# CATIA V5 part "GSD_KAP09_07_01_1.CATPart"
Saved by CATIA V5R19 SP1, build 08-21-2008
Part number: GSD_REPETITION_06
Description: Beispielmodell: Duplizieren eines geometrischen Sets  Maik Hertha IT Consultants
Bounding box of the stored display mesh (mm): x -29.841 to 75.347, y -10 to 40, z 36.232 to 56.986
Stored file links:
  C:\Users\Maik\CAD Daten\modelle\gsd_buch_uebung\GSD_KAP09_07_01_END.CATPart
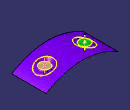
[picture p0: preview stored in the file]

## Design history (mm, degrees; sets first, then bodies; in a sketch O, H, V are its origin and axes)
AxisSystem1 "Absolute Axis System": origin (0, 0, 0), X (1, 0, 0), Y (0, 1, 0), Z (0, 0, 1)
Set1 "Work"
  Plane1: type Equation, A 0, B 1, C 0, Length -10
  Point1: type OnPlane, Support Plane1, Direction (-1, 0, 0), H -16.666, V 8.006
  Sketch1 on Plane1, origin (16.666, -10, 8.006), H (-1, 0, 0), V (0, 0, 1)
    spline S1 through (-58.6807, 28.2259) (-5.4892, 43.7462) (46.5071, 28.2259)
    curve C1
  Extrude1: Lim1 50, Lim2 0, Element1 Sketch1.C1, Direction Plane1
  Set2 "Basis"
    Point2 "Referenzpunkt.1": stored without definition
    Line1 "Ausrichtung.1": type PtDir, Direction (0, 0, 1), Start -10, End 10, RefPoint Point2
    Plane2: type Normal, Curve Line1, RefPoint Point2
    Set3 "Quelle"
      Sketch2 on Plane2, origin (-6.428, 14.4636, 46.9865), H (0, -1, 0), V (1, 0, 0)
        circle A1 centre (0, 0) radius 7.5
        radius A1 = 7.5
      Split1: ToCut Plane2, Intersections {intersect ToIntersect1 Plane2, ToIntersect2 Sketch2}, Cutting Sketch2
      Extrude2: Lim1 13, Lim2 13, Element1 Sketch2, Direction Plane2
      Offset1: Length 5, Offset Extrude2
  Split2: ToCut Extrude1, Intersections {intersect ToIntersect1 Extrude1, ToIntersect2 Offset1}, Cutting Offset1
  Set4 "Ziel"
    Point3 "Referenzpunkt.2": stored without definition
    Line2 "Ausrichtung.2": type PtDir, Direction (0, 0, 1), Start -10, End 10, RefPoint Point3
    Plane3: type Normal, Curve Line2, RefPoint Point3
    Set5 "Quelle"
      Sketch3 on Plane3, origin (51.9218, 14.4636, 46.9574), H (0, -1, 0), V (1, 0, 0)
        circle A1 centre (0, 0) radius 7.5
        radius A1 = 7.5
      Split3: ToCut Plane3, Intersections {intersect ToIntersect1 Plane3, ToIntersect2 Sketch3}, Cutting Sketch3
      Extrude3: Lim1 13, Lim2 13, Element1 Sketch3, Direction Plane3
      Offset2: Length 5, Offset Extrude3
  Split4: ToCut Split2, Intersections {intersect ToIntersect1 Split2, ToIntersect2 Offset2}, Cutting Offset2
  Blend1: StartLimit {blendlimit Support Split4, Curve {intersect ToIntersect1 Extrude1, ToIntersect2 Offset1}, Point {extremum Reference {intersect ToIntersect1 Extrude1, ToIntersect2 Offset1}, Direction (1, 2, 3)}}, EndLimit {blendlimit Support Split1, Curve {intersect ToIntersect1 Plane2, ToIntersect2 Sketch2}, Point {extremum Reference {intersect ToIntersect1 Plane2, ToIntersect2 Sketch2}, Direction (1, 2, 3)}}
  Blend2: StartLimit {blendlimit Support Split3, Curve {intersect ToIntersect1 Plane3, ToIntersect2 Sketch3}, Point {extremum Reference {intersect ToIntersect1 Plane3, ToIntersect2 Sketch3}, Direction (1, 2, 3)}}, EndLimit {blendlimit Support Split4, Curve {intersect ToIntersect1 Split2, ToIntersect2 Offset2}, Point {extremum Reference {intersect ToIntersect1 Split2, ToIntersect2 Offset2}, Direction (1, 2, 3)}}
Body1 (main body)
